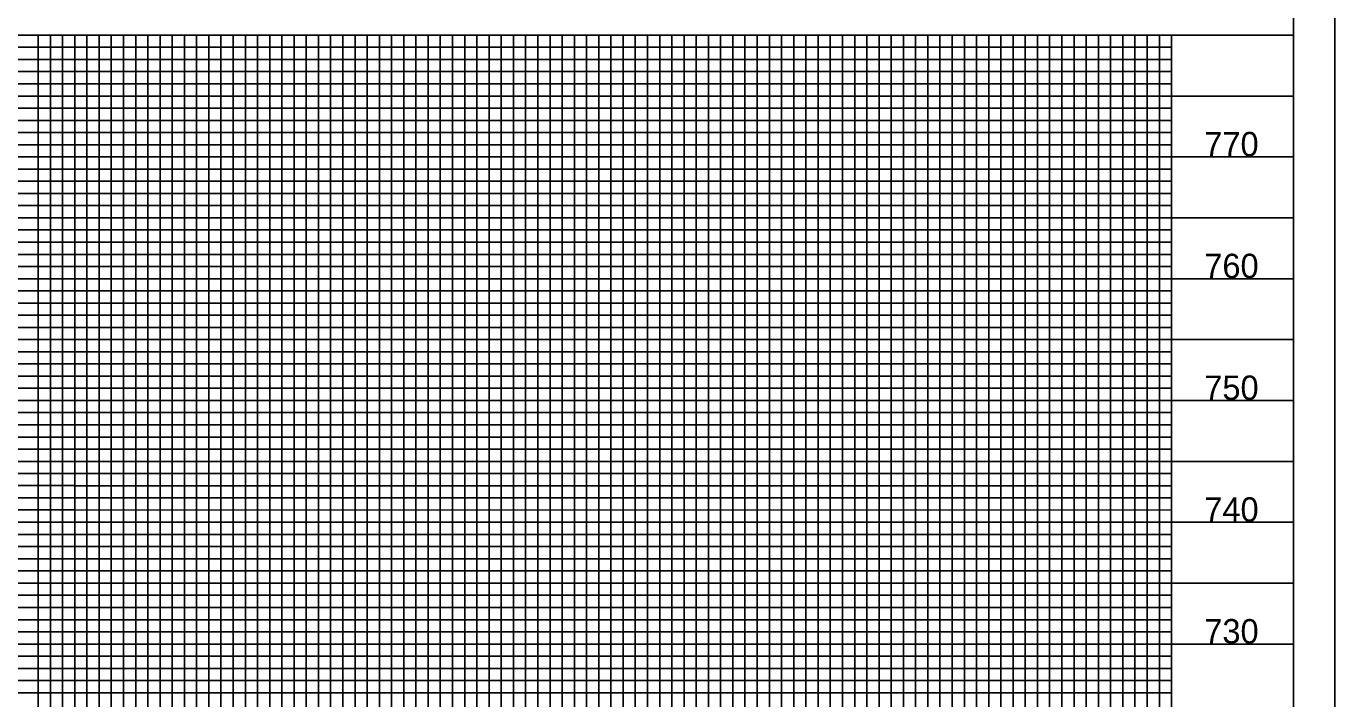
# Model space of a CAD drawing. Extents: x 1524869 to 1526553, y 501099 to 502199.
# Drawn here: x 1526016 to 1526553, y 501376 to 501652 of the extents above; entities that cross this region are included whole.
import ezdxf

# ---------------------------------------------------------------- set-up
doc = ezdxf.new("R2010")
doc.units = 0
for name, color, linetype in [('Exist Vertical Profile Vertical Axis Label', 7, 'Continuous'), ('Sheet Layout Profile Border Port 1', 7, 'Continuous'), ('Sheet Plot Border Outside CELL', 7, 'Continuous'), ('Sheet Profile CELL', 7, 'Continuous'), ('Sheet Profile Grid Major CELL', 7, 'Continuous'), ('Sheet Profile Grid Middle CELL', 7, 'Continuous'), ('Sheet Profile Grid Minor CELL', 7, 'Continuous')]:
    doc.layers.add(name, color=color, linetype=linetype)

msp = doc.modelspace()

# ---------------------------------------------------------------- linework, layer by layer
at = {"layer": 'Sheet Layout Profile Border Port 1'}
msp.add_lwpolyline([(1525536.08, 501648.56), (1526486.08, 501648.56), (1526486.08, 501148.56), (1525536.08, 501148.56)], close=True, dxfattribs=at)
at = {"layer": 'Sheet Plot Border Outside CELL'}
msp.add_lwpolyline([(1524869.08, 501098.56), (1526553.08, 501098.56), (1526553.08, 502198.56), (1524869.08, 502198.56)], close=True, dxfattribs=at)
at = {"layer": 'Sheet Profile CELL'}
msp.add_line((1525036.08, 501648.56), (1526536.08, 501648.56), dxfattribs=at)
msp.add_lwpolyline([(1526536.08, 502173.56), (1525036.08, 502173.56), (1525036.08, 501123.56), (1526536.08, 501123.56)], close=True, dxfattribs=at)
at = {"layer": 'Sheet Profile Grid Major CELL'}
for p, q in [((1526036.08, 501648.56), (1526086.08, 501648.56)), ((1526136.08, 501648.56), (1526186.08, 501648.56)), ((1526236.08, 501648.56), (1526286.08, 501648.56)), ((1526336.08, 501648.56), (1526386.08, 501648.56)), ((1526436.08, 501648.56), (1526486.08, 501648.56))]:
    msp.add_line(p, q, dxfattribs=at)
for points in [[(1525986.08, 501148.56), (1526036.08, 501148.56), (1526036.08, 501648.56), (1526086.08, 501648.56), (1526086.08, 501148.56), (1526136.08, 501148.56), (1526136.08, 501648.56), (1526186.08, 501648.56), (1526186.08, 501148.56), (1526236.08, 501148.56), (1526236.08, 501648.56), (1526286.08, 501648.56), (1526286.08, 501148.56), (1526336.08, 501148.56), (1526336.08, 501648.56), (1526386.08, 501648.56), (1526386.08, 501148.56), (1526436.08, 501148.56), (1526436.08, 501148.56), (1526436.08, 501648.56), (1526486.08, 501648.56), (1526486.08, 501148.56)], [(1526536.08, 501598.56), (1525036.08, 501598.56)], [(1526536.08, 501548.56), (1525036.08, 501548.56), (1525036.08, 501498.56), (1526536.08, 501498.56)], [(1526536.08, 501448.56), (1525036.08, 501448.56), (1525036.08, 501398.56), (1526536.08, 501398.56)]]:
    msp.add_lwpolyline(points, dxfattribs=at)
at = {"layer": 'Sheet Profile Grid Middle CELL'}
for points in [[(1526011.08, 501148.56), (1526061.08, 501148.56), (1526061.08, 501648.56), (1526111.08, 501648.56), (1526111.08, 501148.56), (1526161.08, 501148.56), (1526161.08, 501648.56), (1526211.08, 501648.56), (1526211.08, 501148.56), (1526261.08, 501148.56), (1526261.08, 501648.56), (1526311.08, 501648.56), (1526311.08, 501148.56), (1526361.08, 501148.56), (1526361.08, 501648.56), (1526411.08, 501648.56), (1526411.08, 501148.56), (1526461.08, 501148.56), (1526461.08, 501648.56)], [(1525036.08, 501623.56), (1526536.08, 501623.56)], [(1526536.08, 501573.56), (1525036.08, 501573.56), (1525036.08, 501523.56), (1526536.08, 501523.56)], [(1526536.08, 501473.56), (1525036.08, 501473.56), (1525036.08, 501423.56), (1526536.08, 501423.56)]]:
    msp.add_lwpolyline(points, dxfattribs=at)
at = {"layer": 'Sheet Profile Grid Minor CELL'}
for p, q in [((1525936.08, 501643.56), (1526036.08, 501643.56)), ((1526021.08, 501148.56), (1526021.08, 501648.56)), ((1526026.08, 501148.56), (1526026.08, 501648.56)), ((1526031.08, 501148.56), (1526031.08, 501648.56)), ((1526036.08, 501643.56), (1526486.08, 501643.56)), ((1525936.08, 501638.56), (1526036.08, 501638.56)), ((1526486.08, 501638.56), (1526036.08, 501638.56)), ((1525936.08, 501633.56), (1526036.08, 501633.56)), ((1526036.08, 501633.56), (1526486.08, 501633.56)), ((1525936.08, 501628.56), (1526036.08, 501628.56)), ((1526486.08, 501628.56), (1526036.08, 501628.56)), ((1525936.08, 501618.56), (1526036.08, 501618.56)), ((1526036.08, 501618.56), (1526486.08, 501618.56)), ((1525936.08, 501613.56), (1526036.08, 501613.56)), ((1526486.08, 501613.56), (1526036.08, 501613.56)), ((1525936.08, 501608.56), (1526036.08, 501608.56)), ((1526036.08, 501608.56), (1526486.08, 501608.56)), ((1525936.08, 501603.56), (1526036.08, 501603.56)), ((1526486.08, 501603.56), (1526036.08, 501603.56)), ((1525936.08, 501593.56), (1526036.08, 501593.56)), ((1526036.08, 501593.56), (1526486.08, 501593.56)), ((1525936.08, 501588.56), (1526036.08, 501588.56)), ((1526486.08, 501588.56), (1526036.08, 501588.56)), ((1525936.08, 501583.56), (1526036.08, 501583.56)), ((1526036.08, 501583.56), (1526486.08, 501583.56)), ((1525936.08, 501578.56), (1526036.08, 501578.56)), ((1526486.08, 501578.56), (1526036.08, 501578.56)), ((1525936.08, 501568.56), (1526036.08, 501568.56)), ((1526036.08, 501568.56), (1526486.08, 501568.56)), ((1525936.08, 501563.56), (1526036.08, 501563.56)), ((1526486.08, 501563.56), (1526036.08, 501563.56)), ((1525936.08, 501558.56), (1526036.08, 501558.56)), ((1526036.08, 501558.56), (1526486.08, 501558.56)), ((1525936.08, 501553.56), (1526036.08, 501553.56)), ((1526486.08, 501553.56), (1526036.08, 501553.56)), ((1525936.08, 501543.56), (1526036.08, 501543.56)), ((1526036.08, 501543.56), (1526486.08, 501543.56)), ((1525936.08, 501538.56), (1526036.08, 501538.56)), ((1526486.08, 501538.56), (1526036.08, 501538.56)), ((1525936.08, 501533.56), (1526036.08, 501533.56)), ((1526036.08, 501533.56), (1526486.08, 501533.56)), ((1525936.08, 501528.56), (1526036.08, 501528.56)), ((1526486.08, 501528.56), (1526036.08, 501528.56)), ((1525936.08, 501518.56), (1526036.08, 501518.56)), ((1526036.08, 501518.56), (1526486.08, 501518.56)), ((1525936.08, 501513.56), (1526036.08, 501513.56)), ((1526486.08, 501513.56), (1526036.08, 501513.56)), ((1525936.08, 501508.56), (1526036.08, 501508.56)), ((1526036.08, 501508.56), (1526486.08, 501508.56)), ((1525936.08, 501503.56), (1526036.08, 501503.56)), ((1526486.08, 501503.56), (1526036.08, 501503.56)), ((1525936.08, 501493.56), (1526036.08, 501493.56)), ((1526036.08, 501493.56), (1526486.08, 501493.56)), ((1525936.08, 501488.56), (1526036.08, 501488.56)), ((1526486.08, 501488.56), (1526036.08, 501488.56)), ((1525936.08, 501483.56), (1526036.08, 501483.56)), ((1526036.08, 501483.56), (1526486.08, 501483.56)), ((1525936.08, 501478.56), (1526036.08, 501478.56)), ((1526486.08, 501478.56), (1526036.08, 501478.56)), ((1525936.08, 501468.62), (1526036.08, 501468.62)), ((1526036.08, 501468.56), (1526486.08, 501468.56)), ((1525936.08, 501463.62), (1526036.08, 501463.62)), ((1526486.08, 501463.56), (1526036.08, 501463.56)), ((1525936.08, 501458.62), (1526036.08, 501458.62)), ((1526036.08, 501458.56), (1526486.08, 501458.56)), ((1525936.08, 501453.62), (1526036.08, 501453.62)), ((1526486.08, 501453.56), (1526036.08, 501453.61)), ((1525936.08, 501443.56), (1526036.08, 501443.56)), ((1526036.08, 501443.56), (1526486.08, 501443.56)), ((1525936.08, 501438.56), (1526036.08, 501438.56)), ((1526486.08, 501438.56), (1526036.08, 501438.56)), ((1525936.08, 501433.56), (1526036.08, 501433.56)), ((1526036.08, 501433.56), (1526486.08, 501433.56)), ((1525936.08, 501428.56), (1526036.08, 501428.56)), ((1526486.08, 501428.56), (1526036.08, 501428.56)), ((1525936.08, 501418.56), (1526036.08, 501418.56)), ((1526036.08, 501418.56), (1526486.08, 501418.56)), ((1525936.08, 501413.56), (1526036.08, 501413.56)), ((1526486.08, 501413.56), (1526036.08, 501413.56)), ((1525936.08, 501408.56), (1526036.08, 501408.56)), ((1526036.08, 501408.56), (1526486.08, 501408.56)), ((1525936.08, 501403.56), (1526036.08, 501403.56)), ((1526486.08, 501403.56), (1526036.08, 501403.56)), ((1525936.08, 501393.56), (1526036.08, 501393.56)), ((1526036.08, 501393.56), (1526486.08, 501393.56)), ((1525936.08, 501388.56), (1526036.08, 501388.56)), ((1526486.08, 501388.56), (1526036.08, 501388.56)), ((1525936.08, 501383.56), (1526036.08, 501383.56)), ((1526036.08, 501383.56), (1526486.08, 501383.56)), ((1525936.08, 501378.56), (1526036.08, 501378.56)), ((1526486.08, 501378.56), (1526036.08, 501378.56))]:
    msp.add_line(p, q, dxfattribs=at)
for points in [[(1526031.08, 501648.56), (1526041.08, 501648.56), (1526041.08, 501148.56)], [(1526046.08, 501148.56), (1526046.08, 501648.56), (1526051.08, 501648.56), (1526051.08, 501148.56)], [(1526056.08, 501148.56), (1526056.08, 501648.56), (1526066.08, 501648.56), (1526066.08, 501148.56)], [(1526071.08, 501148.56), (1526071.08, 501648.56), (1526076.08, 501648.56), (1526076.08, 501148.56)], [(1526081.08, 501148.56), (1526081.08, 501648.56), (1526091.08, 501648.56), (1526091.08, 501148.56)], [(1526096.08, 501148.56), (1526096.08, 501648.56), (1526101.08, 501648.56), (1526101.08, 501148.56)], [(1526106.08, 501148.56), (1526106.08, 501648.56), (1526116.08, 501648.56), (1526116.08, 501148.56)], [(1526121.08, 501148.56), (1526121.08, 501648.56), (1526126.08, 501648.56), (1526126.08, 501148.56)], [(1526131.08, 501148.56), (1526131.08, 501648.56), (1526141.08, 501648.56), (1526141.08, 501148.56)], [(1526146.08, 501148.56), (1526146.08, 501648.56), (1526151.08, 501648.56), (1526151.08, 501148.56)], [(1526156.08, 501148.56), (1526156.08, 501648.56), (1526166.08, 501648.56), (1526166.08, 501148.56)], [(1526171.08, 501148.56), (1526171.08, 501648.56), (1526176.08, 501648.56), (1526176.08, 501148.56)], [(1526181.08, 501148.56), (1526181.08, 501648.56), (1526191.08, 501648.56), (1526191.08, 501148.56)], [(1526196.08, 501148.56), (1526196.08, 501648.56), (1526201.08, 501648.56), (1526201.08, 501148.56)], [(1526206.08, 501148.56), (1526206.08, 501648.56), (1526216.08, 501648.56), (1526216.08, 501148.56)], [(1526221.08, 501148.56), (1526221.08, 501648.56), (1526226.08, 501648.56), (1526226.08, 501148.56)], [(1526231.08, 501148.56), (1526231.08, 501648.56), (1526241.08, 501648.56), (1526241.08, 501148.56)], [(1526246.08, 501148.56), (1526246.08, 501648.56), (1526251.08, 501648.56), (1526251.08, 501148.56)], [(1526256.08, 501148.56), (1526256.08, 501648.56), (1526266.08, 501648.56), (1526266.08, 501148.56)], [(1526271.08, 501148.56), (1526271.08, 501648.56), (1526276.08, 501648.56), (1526276.08, 501148.56)], [(1526281.08, 501148.56), (1526281.08, 501648.56), (1526291.08, 501648.56), (1526291.08, 501148.56)], [(1526296.08, 501148.56), (1526296.08, 501648.56), (1526301.08, 501648.56), (1526301.08, 501148.56)], [(1526306.08, 501148.56), (1526306.08, 501648.56), (1526316.08, 501648.56), (1526316.08, 501148.56)], [(1526321.08, 501148.56), (1526321.08, 501648.56), (1526326.08, 501648.56), (1526326.08, 501148.56)], [(1526331.08, 501148.56), (1526331.08, 501648.56), (1526341.08, 501648.56), (1526341.08, 501148.56)], [(1526346.08, 501148.56), (1526346.08, 501648.56), (1526351.08, 501648.56), (1526351.08, 501148.56)], [(1526356.08, 501148.56), (1526356.08, 501648.56), (1526366.08, 501648.56), (1526366.08, 501148.56)], [(1526371.08, 501148.56), (1526371.08, 501648.56), (1526376.08, 501648.56), (1526376.08, 501148.56)], [(1526381.08, 501148.56), (1526381.08, 501648.56), (1526391.08, 501648.56), (1526391.08, 501148.56)], [(1526396.08, 501148.56), (1526396.08, 501648.56), (1526401.08, 501648.56), (1526401.08, 501148.56)], [(1526406.08, 501148.56), (1526406.08, 501648.56), (1526416.08, 501648.56), (1526416.08, 501148.56)], [(1526421.08, 501148.56), (1526421.08, 501648.56), (1526426.08, 501648.56), (1526426.08, 501148.56)], [(1526431.08, 501148.56), (1526431.08, 501648.56), (1526441.08, 501648.56), (1526441.08, 501148.56)], [(1526446.08, 501148.56), (1526446.08, 501648.56), (1526451.08, 501648.56), (1526451.08, 501148.56)], [(1526456.08, 501148.56), (1526456.08, 501648.56), (1526466.08, 501648.56), (1526466.08, 501148.56)], [(1526471.08, 501148.56), (1526471.08, 501648.56), (1526476.08, 501648.56), (1526476.08, 501148.56)], [(1526481.08, 501148.56), (1526481.08, 501648.56), (1526486.08, 501648.56)]]:
    msp.add_lwpolyline(points, dxfattribs=at)

# ---------------------------------------------------------------- texts
at = {"layer": 'Exist Vertical Profile Vertical Axis Label'}
for s, p in [('770', (1526499.51, 501598.81)), ('760', (1526499.51, 501548.81)), ('750', (1526499.51, 501498.81)), ('740', (1526499.51, 501448.81)), ('730', (1526499.51, 501398.81))]:
    msp.add_text(s, height=10, dxfattribs=at).set_placement(p)

doc.saveas('drawing.dxf')
